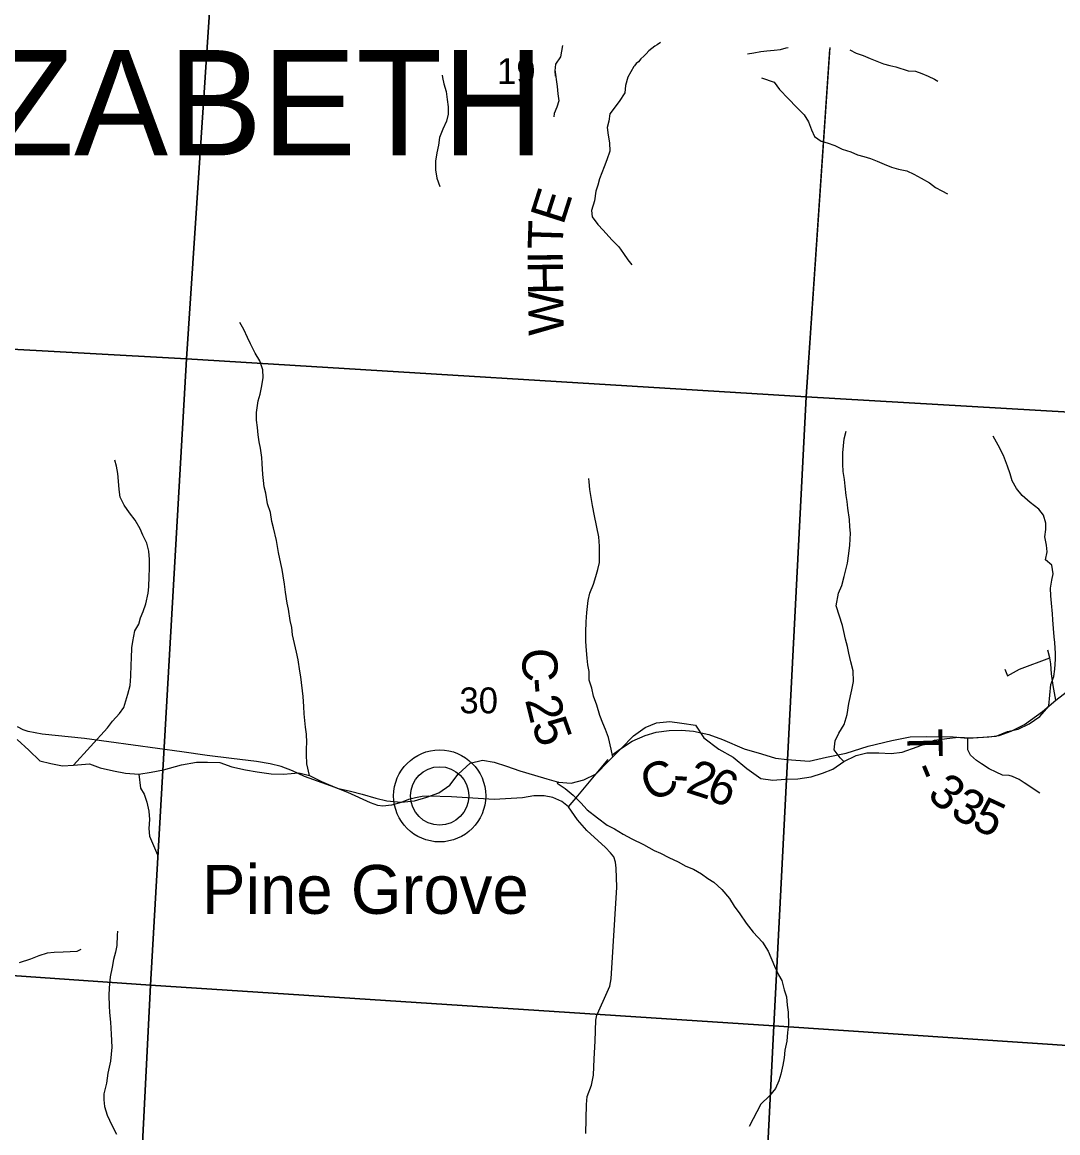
# Model space of a CAD drawing. Extents: x 0 to 82.7, y -0.2 to 22.
# Drawn here: x 5.374 to 7.048, y 15.035 to 16.831 of the extents above; entities that cross this region are included whole.
import ezdxf

# ---------------------------------------------------------------- set-up
doc = ezdxf.new("R2010")
doc.units = 0
for name, color, linetype in [('GM_X_County_Road', 7, 'Continuous'), ('GM_X_County_Road_Text', 7, 'Continuous'), ('GM_X_Minor_River', 7, 'Continuous'), ('GM_X_Section', 7, 'Continuous'), ('GM_X_Section_Text', 7, 'Continuous'), ('GM_X_State_Route', 7, 'Continuous'), ('GM_X_Township_Road', 7, 'Continuous'), ('GM_X_Township_Road_Text', 7, 'Continuous'), ('GM_X_Township_Text', 7, 'Continuous'), ('GM_X_Unincorporated', 7, 'Continuous'), ('GM_X_Unincorporated_Location', 7, 'Continuous'), ('GM_X_Unincorporated_Text', 7, 'Continuous')]:
    doc.layers.add(name, color=color, linetype=linetype)

msp = doc.modelspace()

# ---------------------------------------------------------------- linework, layer by layer
at = {"layer": 'GM_X_County_Road'}
for points in [[(6.3275, 15.6465), (6.3407, 15.6561), (6.3596, 15.6682), (6.3808, 15.6777), (6.3985, 15.683), (6.4195, 15.6857), (6.4395, 15.6862), (6.4586, 15.6846), (6.4835, 15.679), (6.5058, 15.6709), (6.5405, 15.6562), (6.5685, 15.6479), (6.5912, 15.6411), (6.6102, 15.6388), (6.6459, 15.6361), (6.674, 15.6424), (6.7055, 15.649), (6.741, 15.6601), (6.7793, 15.6696), (6.8089, 15.6756), (6.8358, 15.676), (6.8783, 15.6752), (6.9022, 15.6735), (6.9361, 15.6753), (6.953, 15.6776), (6.9721, 15.6844), (6.9939, 15.6954), (7.0228, 15.7166), (7.0445, 15.7347), (7.0802, 15.762)], [(6.2568, 15.5622), (6.2721, 15.5798), (6.2932, 15.6061), (6.3148, 15.632), (6.3208, 15.6389)]]:
    msp.add_lwpolyline(points, dxfattribs=at)
at = {"layer": 'GM_X_Minor_River'}
for points in [[(6.2468, 16.7935), (6.2439, 16.775), (6.2359, 16.7629), (6.2347, 16.7523), (6.2354, 16.7436)], [(6.4055, 16.7984), (6.4055, 16.7983), (6.4001, 16.7946), (6.3963, 16.7923), (6.3917, 16.7886), (6.3867, 16.7845), (6.3821, 16.7796), (6.3783, 16.7762), (6.3737, 16.7717), (6.3698, 16.7668), (6.366, 16.7642), (6.3633, 16.7605), (6.3626, 16.7596)], [(6.546, 16.7801), (6.5564, 16.7816), (6.5674, 16.7834), (6.5773, 16.7849), (6.589, 16.7859), (6.5992, 16.7866), (6.6087, 16.7896), (6.6119, 16.7902)], [(6.7113, 16.7862), (6.7215, 16.7809), (6.7332, 16.777), (6.7446, 16.7724), (6.7657, 16.7639), (6.7759, 16.7611), (6.7861, 16.7588), (6.8058, 16.7526), (6.8175, 16.7518), (6.8277, 16.7479), (6.8383, 16.744), (6.8481, 16.7387), (6.8538, 16.7356)], [(6.3626, 16.7596), (6.3526, 16.742), (6.3491, 16.7287), (6.3476, 16.7166), (6.3388, 16.703), (6.3236, 16.6826), (6.3217, 16.6712), (6.319, 16.661), (6.3209, 16.6484), (6.3231, 16.6359), (6.3235, 16.6223), (6.3185, 16.6086), (6.3143, 16.5969), (6.3067, 16.5779), (6.304, 16.5673), (6.301, 16.5579), (6.2987, 16.5423), (6.2941, 16.5264), (6.2948, 16.5165), (6.3039, 16.504), (6.3129, 16.4945), (6.3269, 16.4793), (6.3379, 16.4675), (6.3458, 16.4572), (6.3526, 16.4469), (6.3593, 16.4386)], [(6.0525, 16.7451), (6.0529, 16.7418), (6.0552, 16.7316), (6.059, 16.7187), (6.0609, 16.7058), (6.062, 16.6944), (6.0624, 16.6823), (6.0597, 16.6709), (6.0537, 16.658), (6.048, 16.6443), (6.0465, 16.6322), (6.0438, 16.6197), (6.0416, 16.6064), (6.0416, 16.5924), (6.0438, 16.5787), (6.0487, 16.5655)], [(6.2349, 16.7542), (6.2382, 16.7272), (6.2397, 16.7151), (6.2412, 16.7037), (6.2378, 16.6935), (6.2336, 16.6833), (6.2332, 16.6779)], [(6.5686, 16.7409), (6.5891, 16.7343), (6.5978, 16.7222), (6.6121, 16.7073), (6.6253, 16.6936), (6.6378, 16.6811), (6.6446, 16.67), (6.6498, 16.6568), (6.6543, 16.6461), (6.6653, 16.6389), (6.6751, 16.6362), (6.6872, 16.6316), (6.6993, 16.6259), (6.7129, 16.6213), (6.7239, 16.6163), (6.7341, 16.6136), (6.7447, 16.6105), (6.7557, 16.6063), (6.767, 16.6017), (6.7787, 16.5964), (6.7901, 16.5933), (6.8037, 16.5906), (6.8147, 16.5853), (6.8267, 16.5788), (6.84, 16.5715), (6.8502, 16.5635), (6.86, 16.5582), (6.8691, 16.5532)], [(5.8381, 15.6129), (5.8338, 15.6317), (5.8335, 15.6468), (5.8335, 15.6563), (5.8338, 15.6662), (5.8331, 15.6798), (5.8316, 15.6912), (5.8297, 15.7124), (5.8289, 15.7246), (5.8278, 15.7405), (5.824, 15.7724), (5.8225, 15.7818), (5.8199, 15.7997), (5.8169, 15.8122), (5.8138, 15.8262), (5.8108, 15.8406), (5.8093, 15.852), (5.807, 15.8634), (5.804, 15.8816), (5.8021, 15.8914), (5.7995, 15.9096), (5.7976, 15.9221), (5.7953, 15.9358), (5.7938, 15.946), (5.7919, 15.9559), (5.7882, 15.9733), (5.7848, 15.9927), (5.7799, 16.0135), (5.7772, 16.0238), (5.7749, 16.0382), (5.7704, 16.0522), (5.7674, 16.0696), (5.7647, 16.0799), (5.764, 16.0901), (5.7625, 16.0996), (5.7617, 16.1174), (5.761, 16.1269), (5.7587, 16.1421), (5.7568, 16.1527), (5.7553, 16.1637), (5.7542, 16.1758), (5.7527, 16.1876), (5.7527, 16.1997), (5.7549, 16.2187), (5.7584, 16.2297), (5.761, 16.243), (5.7633, 16.2566), (5.7625, 16.2687), (5.7576, 16.2832), (5.7504, 16.2957), (5.7425, 16.3108), (5.738, 16.3214), (5.7319, 16.3343), (5.7256, 16.3455)], [(6.702, 15.6357), (6.6957, 15.6412), (6.6862, 15.6545), (6.6878, 15.6689), (6.6938, 15.6811), (6.7021, 15.6955), (6.707, 15.7118), (6.7101, 15.7292), (6.7146, 15.7512), (6.7176, 15.7649), (6.7169, 15.782), (6.7131, 15.7967), (6.7097, 15.8108), (6.7078, 15.8214), (6.7044, 15.8331), (6.7018, 15.846), (6.6999, 15.8555), (6.6893, 15.8874), (6.6931, 15.9075), (6.6984, 15.92), (6.7026, 15.9348), (6.7079, 15.9564), (6.7097, 15.972), (6.7113, 15.9852), (6.7124, 16.0049), (6.7116, 16.0152), (6.7109, 16.0266), (6.7083, 16.0451), (6.7071, 16.0558), (6.7056, 16.0656), (6.7037, 16.0808), (6.703, 16.0914), (6.7007, 16.1043), (6.7, 16.1164), (6.7003, 16.1346), (6.7022, 16.1574), (6.7056, 16.1699)], [(7.0331, 15.7253), (7.0363, 15.7598), (7.0412, 15.7731), (7.0431, 15.7848), (7.0439, 15.8008), (7.0439, 15.8102), (7.0431, 15.8277), (7.042, 15.8372), (7.0409, 15.8504), (7.0397, 15.8645), (7.039, 15.8743), (7.0375, 15.8914), (7.0363, 15.9032), (7.036, 15.916), (7.0379, 15.9286), (7.0401, 15.9392), (7.0379, 15.9532), (7.028, 15.9616), (7.0303, 15.9748), (7.0292, 15.9851), (7.0265, 15.9987), (7.0281, 16.0109), (7.0284, 16.0207), (7.0243, 16.034), (7.0171, 16.0438), (7.0031, 16.0544), (6.9903, 16.0654), (6.9808, 16.0772), (6.974, 16.0893), (6.9706, 16.1007), (6.9661, 16.1132), (6.9597, 16.1303), (6.9513, 16.1473), (6.943, 16.1617)], [(5.4565, 15.6296), (5.5114, 15.6899), (5.5197, 15.7005), (5.5311, 15.7134), (5.5379, 15.7229), (5.5443, 15.7445), (5.5481, 15.7582), (5.5492, 15.7737), (5.55, 15.7919), (5.5504, 15.8026), (5.5507, 15.8192), (5.5523, 15.8295), (5.556, 15.8466), (5.5621, 15.8576), (5.5647, 15.8678), (5.5693, 15.878), (5.5738, 15.8906), (5.5772, 15.908), (5.5784, 15.9182), (5.5787, 15.9345), (5.5795, 15.9478), (5.5795, 15.9622), (5.5784, 15.9755), (5.575, 15.9884), (5.5685, 16.0017), (5.5644, 16.0119), (5.5561, 16.0259), (5.547, 16.0377), (5.5387, 16.0502), (5.5319, 16.0631), (5.5304, 16.0756), (5.5296, 16.0889), (5.5285, 16.101), (5.5259, 16.1131), (5.5236, 16.123)], [(6.3283, 15.6428), (6.3256, 15.6556), (6.3214, 15.6741), (6.3166, 15.6874), (6.3124, 15.6973), (6.3075, 15.7098), (6.3023, 15.7266), (6.297, 15.741), (6.2944, 15.7539), (6.2903, 15.7668), (6.2903, 15.7808), (6.2881, 15.7918), (6.287, 15.8028), (6.2858, 15.815), (6.2847, 15.8298), (6.2848, 15.8446), (6.2852, 15.8616), (6.2864, 15.8764), (6.2887, 15.8957), (6.2914, 15.9075), (6.2971, 15.9223), (6.3009, 15.9348), (6.3043, 15.9461), (6.3066, 15.9575), (6.3067, 15.9693), (6.3071, 15.984), (6.306, 15.9988), (6.2989, 16.0326), (6.2955, 16.0493), (6.2933, 16.0626), (6.2914, 16.0751), (6.2903, 16.088), (6.2896, 16.0929)], [(5.3658, 15.6712), (5.3847, 15.654), (5.402, 15.6365), (5.4198, 15.6323), (5.4387, 15.6285), (5.4565, 15.6296), (5.4826, 15.6315), (5.5, 15.6254), (5.5212, 15.6204), (5.5409, 15.6166), (5.5625, 15.6151), (5.5822, 15.6181), (5.6019, 15.6219), (5.6314, 15.6302), (5.6553, 15.6347), (5.6731, 15.6343), (5.6931, 15.634), (5.7128, 15.6271), (5.7347, 15.6221), (5.7533, 15.6187), (5.7764, 15.6156), (5.796, 15.6152), (5.8207, 15.6171), (5.8381, 15.6129), (5.8573, 15.6034), (5.8831, 15.5923), (5.9046, 15.5874), (5.9232, 15.5828), (5.9451, 15.5763), (5.9629, 15.5721), (5.9864, 15.5698), (6.0076, 15.572), (6.0276, 15.5781), (6.047, 15.5846), (6.0652, 15.5975), (6.0785, 15.6153), (6.0978, 15.6328), (6.1179, 15.6377), (6.1368, 15.6343), (6.1568, 15.6278), (6.178, 15.6206), (6.2019, 15.6133), (6.2215, 15.6076), (6.2408, 15.6019), (6.2609, 15.6003), (6.2817, 15.606), (6.3014, 15.6155), (6.3215, 15.636), (6.342, 15.6565), (6.3618, 15.6771), (6.3807, 15.6907), (6.3989, 15.6979), (6.4205, 15.7002), (6.4398, 15.6975), (6.4621, 15.6941), (6.4753, 15.6739), (6.4995, 15.6556), (6.5229, 15.6427), (6.5452, 15.6244), (6.5675, 15.608), (6.5868, 15.6054), (6.6069, 15.6069), (6.6273, 15.6076), (6.6489, 15.611), (6.6671, 15.6167), (6.6842, 15.6232), (6.702, 15.6357), (6.7217, 15.6452), (6.7391, 15.6497), (6.7581, 15.6497), (6.7785, 15.6486), (6.7959, 15.6504), (6.8205, 15.6592), (6.8486, 15.6702), (6.8683, 15.6728), (6.8872, 15.6747), (6.9073, 15.6739), (6.9266, 15.6751), (6.9478, 15.6766), (6.9663, 15.6838), (6.9838, 15.6879), (7.0016, 15.6967), (7.0186, 15.7081), (7.0331, 15.7252), (7.0331, 15.7253)], [(5.5625, 15.6151), (5.5647, 15.5925), (5.5707, 15.5826), (5.5753, 15.5697), (5.5783, 15.5553), (5.5794, 15.5417), (5.5783, 15.5272), (5.5794, 15.5147), (5.5923, 15.4844)], [(6.2408, 15.6019), (6.2387, 15.6004), (6.2511, 15.5921), (6.2644, 15.5811), (6.2768, 15.5686), (6.2867, 15.5572), (6.3037, 15.5447), (6.3195, 15.5326), (6.3309, 15.5265), (6.3452, 15.5182), (6.3592, 15.5106), (6.3778, 15.5011), (6.3951, 15.4916), (6.4057, 15.4871), (6.419, 15.4803), (6.4341, 15.4735), (6.4465, 15.4663), (6.4586, 15.4617), (6.4719, 15.4538), (6.4817, 15.4462), (6.4919, 15.4405), (6.5044, 15.4284), (6.5168, 15.414), (6.5248, 15.4015), (6.5335, 15.3893), (6.5441, 15.3742), (6.555, 15.3594), (6.5705, 15.3435), (6.5796, 15.329), (6.5898, 15.3048), (6.5962, 15.2908), (6.6015, 15.2813), (6.6053, 15.2665), (6.609, 15.2551), (6.6102, 15.2415), (6.6117, 15.2301), (6.6124, 15.21), (6.6109, 15.1975), (6.6094, 15.1831), (6.6064, 15.1686), (6.6056, 15.1565), (6.6034, 15.1444), (6.5999, 15.13), (6.5965, 15.119), (6.5912, 15.1068), (6.5814, 15.0951), (6.5678, 15.0814), (6.5489, 15.0451)], [(5.5276, 15.3612), (5.5272, 15.3547), (5.5265, 15.338), (5.5246, 15.327), (5.5215, 15.3152), (5.5193, 15.3027), (5.5159, 15.2872), (5.5143, 15.2693), (5.514, 15.2572), (5.5143, 15.2405), (5.5151, 15.2295), (5.5162, 15.214), (5.5177, 15.1946), (5.5185, 15.1734), (5.5166, 15.151), (5.5124, 15.1313), (5.5098, 15.1154), (5.5056, 15.0979), (5.5056, 15.0884), (5.5067, 15.0778), (5.5109, 15.0634), (5.5185, 15.0475), (5.5264, 15.0327)], [(5.4686, 15.3315), (5.4618, 15.3281), (5.4512, 15.3277), (5.4399, 15.3273), (5.4255, 15.3266), (5.4142, 15.3254), (5.4006, 15.3212), (5.3873, 15.3159), (5.3688, 15.3098)]]:
    msp.add_lwpolyline(points, dxfattribs=at)
at = {"layer": 'GM_X_Section'}
for points in [[(4.7026, 17.3656), (5.7068, 17.3032), (5.6394, 16.2869), (4.6367, 16.3423)], [(4.6367, 16.3423), (5.6394, 16.2869), (5.5813, 15.2736), (4.5831, 15.3434)], [(5.6394, 16.2869), (6.6409, 16.2254), (6.5889, 15.2079), (5.5813, 15.2736)], [(6.6409, 16.2254), (7.6497, 16.1665), (7.6018, 15.1403), (6.5889, 15.2079)], [(5.5813, 15.2736), (5.5292, 14.2515), (4.5265, 14.3104), (4.5831, 15.3434)], [(6.5889, 15.2079), (6.5375, 14.1911), (5.5292, 14.2515), (5.5813, 15.2736)], [(7.6018, 15.1403), (7.5478, 14.1251), (6.5375, 14.1911), (6.5889, 15.2079)]]:
    msp.add_lwpolyline(points, close=True, dxfattribs=at)
for points in [[(6.6791, 16.7901), (6.6409, 16.2254), (5.6394, 16.2869), (5.7068, 17.3032), (6.099, 17.2784)], [(6.7452, 17.2376), (7.7171, 17.1775), (7.6497, 16.1665), (6.6409, 16.2254), (6.6789, 16.7875)]]:
    msp.add_lwpolyline(points, dxfattribs=at)
at = {"layer": 'GM_X_State_Route'}
for points in [[(6.2568, 15.5622), (6.2462, 15.5706), (6.2317, 15.5771), (6.2173, 15.5799), (6.2009, 15.5802), (6.1826, 15.5768), (6.1365, 15.574), (6.0679, 15.5785), (6.0307, 15.5797), (6.0204, 15.5792), (6.0094, 15.5768), (5.9983, 15.5739), (5.9863, 15.5693), (5.9705, 15.5651), (5.9564, 15.5635), (5.9483, 15.5645), (5.9366, 15.5688), (5.9001, 15.5853), (5.8797, 15.5937), (5.83, 15.6111), (5.8106, 15.6203), (5.7924, 15.6277), (5.7748, 15.6319), (5.7525, 15.6355), (5.7123, 15.6402), (5.6729, 15.6453), (5.632, 15.651), (5.4744, 15.6729), (5.4058, 15.6799), (5.3833, 15.6843), (5.3752, 15.6869), (5.366, 15.6917)], [(6.2849, 15.0342), (6.2856, 15.0811), (6.2869, 15.0939), (6.2942, 15.1123), (6.297, 15.1283), (6.2981, 15.1549), (6.2998, 15.1834), (6.3012, 15.2173), (6.3026, 15.2251), (6.3056, 15.2323), (6.3172, 15.2577), (6.3234, 15.2725), (6.3256, 15.284), (6.3348, 15.4325), (6.334, 15.4632), (6.3325, 15.4726), (6.3298, 15.4814), (6.3244, 15.4881), (6.3163, 15.4967), (6.2865, 15.5239), (6.2715, 15.5414), (6.2568, 15.5622)]]:
    msp.add_lwpolyline(points, dxfattribs=at)
at = {"layer": 'GM_X_Township_Road'}
for points in [[(7.0445, 15.7347), (7.0404, 15.7583), (7.0374, 15.7772), (7.0364, 15.7937), (7.0345, 15.8033), (7.0316, 15.8158)], [(6.9622, 15.7851), (6.9663, 15.7742), (6.9859, 15.7847), (7.0345, 15.8033)], [(7.0187, 15.5842), (6.9932, 15.6012), (6.9853, 15.6062), (6.9744, 15.6111), (6.9692, 15.6127), (6.9581, 15.6137), (6.9479, 15.6184), (6.9368, 15.6239), (6.9241, 15.6319), (6.916, 15.6374), (6.9064, 15.6458), (6.9023, 15.6543), (6.9022, 15.6735)]]:
    msp.add_lwpolyline(points, dxfattribs=at)
at = {"layer": 'GM_X_Unincorporated'}
for radius in [0.0744, 0.0472]:
    msp.add_circle((6.0485, 15.5799), radius, dxfattribs=at)
at = {"layer": 'GM_X_Unincorporated_Location'}
msp.add_line((6.0485, 15.5799), (6.0485, 15.5799), dxfattribs=at)

# ---------------------------------------------------------------- texts
at = {"layer": 'GM_X_County_Road_Text'}
for s, rotation, p in [('E', 72.3572, (6.2481, 16.5016)), ('T', 88.1311, (6.2474, 16.4631)), ('I', 90.6791, (6.2477, 16.4405)), ('H', 90.8561, (6.2484, 16.3905)), ('W', 90.8632, (6.2494, 16.3247)), ('C', 271.7566, (6.1814, 15.8182)), ('-', 274.1186, (6.183, 15.769)), ('2', 283.9778, (6.1863, 15.7352)), ('5', 289.514, (6.1965, 15.6955)), ('C', 23.8061, (6.389, 15.5695)), ('2', 342.1468, (6.4443, 15.5864)), ('6', 337.8005, (6.4765, 15.5761)), ('-', 356.485, (6.4247, 15.5871))]:
    msp.add_text(s, height=0.0568, rotation=rotation, dxfattribs=at).set_placement(p)
at = {"layer": 'GM_X_Section_Text'}
for s, p in [('19', (6.1413, 16.7309)), ('30', (6.0805, 15.7134))]:
    msp.add_text(s, height=0.04186, rotation=0, dxfattribs=at).set_placement(p)
at = {"layer": 'GM_X_Township_Road_Text'}
for s, rotation, p in [('T', 271.3244, (6.804, 15.688)), ('-', 292.6521, (6.8097, 15.6231)), ('3', 318.2782, (6.8346, 15.5792)), ('3', 330.6938, (6.8717, 15.5481)), ('5', 334.9761, (6.9063, 15.5289))]:
    msp.add_text(s, height=0.0568, rotation=rotation, dxfattribs=at).set_placement(p)
at = {"layer": 'GM_X_Township_Text'}
msp.add_text('ELIZABETH', height=0.17045, rotation=0, dxfattribs=at).set_placement((4.9762, 16.6155))
at = {"layer": 'GM_X_Unincorporated_Text'}
msp.add_text('Pine Grove', height=0.07898, rotation=0, dxfattribs=at).set_placement((5.6642, 15.3892))

doc.saveas('drawing.dxf')
